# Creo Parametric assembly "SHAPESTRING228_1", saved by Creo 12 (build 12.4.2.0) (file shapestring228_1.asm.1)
Units: Custom; MM, KILOGRAM, SECS

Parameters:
  PTC_WM_ITERATION = "0"
  PTC_WM_VERSION = "-.0"
  PTC_WM_LIFECYCLE_STATE = "In Work"
  PTC_WM_LIFECYCLE = "MO_CADDocument"
  PTC_WM_CREATED_BY = "Maximilian Roepper (Z0017RMS: MO)"
  PTC_WM_CREATED_ON = "18-Sep-26 11:36:42 AM"
  PTC_WM_MODIFIED_BY = "Maximilian Roepper (Z0017RMS: MO)"
  PTC_WM_MODIFIED_ON = "18-Sep-26 11:36:46 AM"
  PDMLINKNUMBER = "PDM000071455184"
  PTC_WM_NAME = "shapestring228_1.asm"
  PTC_WM_NUMBER = "PDM000071455184"

Other parameters: WEIGHT, WEIGHT_FACTOR, WEIGHT_ADD, MC_ERRORS, SUPPLIER, ISPOSITIONINGASSEMBLY

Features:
  1. coordinate system
  2. imported feature
  3. component "SHAPESTRING089_1"
  4. component "SHAPESTRING227_1"

Other named items: DRW_VIEW_ORG, ROUGH-GROB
